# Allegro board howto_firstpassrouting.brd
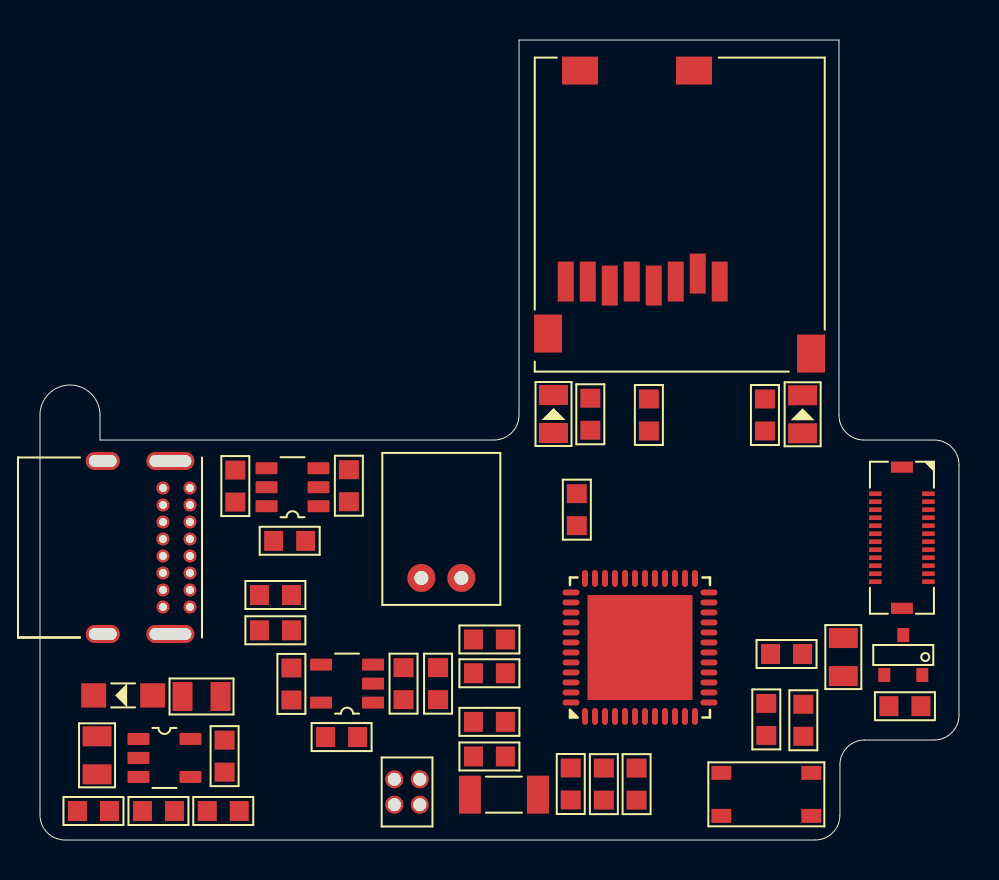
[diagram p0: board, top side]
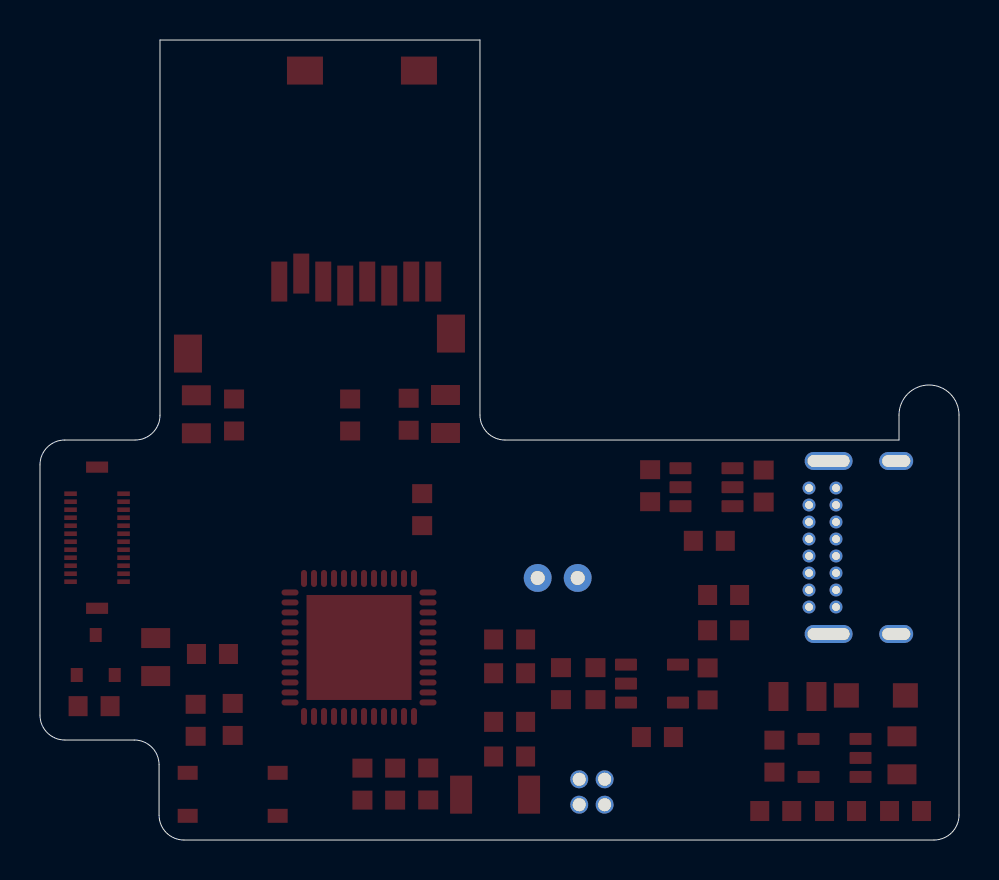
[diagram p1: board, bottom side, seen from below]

Outline 45.95 x 40 mm; copper layers: TOP, L2, L3, BOTTOM. Coordinates in mm from the lower left corner of the outline.
Outline path: 0,21.25 0,1.25 arc(0.37,0.37) 1.25,0 38.76,0 arc(39.64,0.36) 40,1.24 40,3.76 arc(40.36,4.64) 41.24,5 44.71,5 arc(45.59,5.36) 45.95,6.24 45.95,18.76 arc(45.59,19.64) 44.71,20 41.19,20 arc(40.32,20.36) 39.95,21.24 39.95,40 23.95,40 23.95,21.25 arc(23.59,20.37) 22.7,20 3,20 3,21.25 arc(1.5,22.75) 0,21.25

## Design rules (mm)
constraint set DEFAULT: min track width 0.127

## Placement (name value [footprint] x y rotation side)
C15  1uF  [CAP0603]  9.77 17.7 90 top
C16  1uF  [CAP0603]  18.18 7.82 270 top
C19  10uF  [CAP0805]  2.85 4.23 270 top
C20  2.2uF  [CAP0603]  12.57 7.8 90 top
C21  470pF  [CAP0603]  15.08 5.15 0 top
C23  100nF  [CAP0603]  22.47 8.34 180 top
C24  100nF  [CAP0603]  26.84 16.52 90 top
C25  100nF  [CAP0603]  37.33 9.3 0 top
C26  100nF  [CAP0603]  29.83 2.79 270 top
C27  1uF  [CAP0603]  22.47 10.03 180 top
C28  1uF  [CAP0603]  28.2 2.79 270 top
C29  100nF  [CAP0603]  36.32 6.03 90 top
C32  1uF  [CAP0603]  9.23 4.19 270 top
C33  9pF  [CAP0603]  22.47 4.18 180 top
C34  9pF  [CAP0603]  26.54 2.8 90 top
D1  GREEN  [DIO0805]  38.14 21.29 90 top
D2  GREEN  [DIO0805]  25.68 21.3 90 top
D3  SCHOTTKY_DIODE  [SOD-123FL]  4.16 7.23 180 top
J1  -  [USB4085-GF-A]  1.4 14.63 270 top
J2  HEADER VERT 2X2  [2X2-HEADER-50MIL-VERT]  18.36 2.4 270 top
J3  DF37NB-24DS-0.4V  [DF37NB-24DS-0]  43.1 15.11 270 top
J4  2-PIN-CON  [S2B-PH-K]  19.07 13.1 0 top
L1  10uH  [IND0805]  8.08 7.18 180 top
M2  NMOS  [SOT-23-3]  43.17 9.25 0 top
R7  86.6k  [RES0603]  2.67 1.45 0 top
R8  10k  [RES0603]  5.92 1.45 0 top
R9  5.1k  [RES0603]  11.77 10.49 0 top
R10  5.1k  [RES0603]  11.77 12.25 0 top
R11  5.1k  [RES0603]  12.49 14.96 180 top
R12  10k  [RES0603]  38.17 5.99 270 top
R13  10k  [RES0603]  9.16 1.45 0 top
R14  10k  [RES0603]  36.25 21.25 270 top
R15  1.5k  [RES0603]  27.52 21.29 270 top
R16  100k  [RES0603]  19.9 7.82 270 top
R17  100k  [RES0603]  22.47 5.91 0 top
R18  10k  [RES0603]  30.45 21.25 270 top
R19  150R  [RES0805]  40.17 9.15 90 top
R20  10k  [RES0603]  43.25 6.69 0 top
R21  10k  [RES0603]  15.45 17.71 90 top
S1  SPST-NO  [PTS815-SJM-250-SMTR-LFS]  36.32 2.28 0 top
SD2  -  [MEM2061]  30.14 27.92 0 top
U2  BQ21040  [SOT-23-6]  12.63 17.64 180 top
U4  MIC5205-3.3YM5-TR  [SOT-23-5]  15.35 7.82 180 top
U5  AP3012_IC  [SOT-23-5]  6.22 4.1 0 top
U7  ATSAMD21G18A-MF  [48QFN_7X7]  30 9.63 90 top
Y2  32.768 kHz  [2-SMD]  23.2 2.27 0 top

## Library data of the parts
C15 C16 C19-C21 C23-C29 C32-C34 = CAP1: tolerance: 10%
D1 D2 = SML-210MTT86
D3 = SCHOTTKY_DIODE
J1 = USB4085-GF-A
J2 = HEADER VERT 2X2
J3 = DF37NB-24DS-0.4V
J4 = 2-PIN-CON
L1 = IND: tolerance: 20%
M2 = NMOS
R7-R21 = RES1: tolerance: 1%
S1 = PTS815 SJM 250 SMTR LFS
SD2 = MEM2061
U2 = BQ21040
U4 = MIC5205-3.3YM5-TR
U5 = AP3012_IC
U7 = ATSAMD21G18A-MF
Y2 = CC5V-T1A-32.768KHZ-9PF: tolerance: 20%

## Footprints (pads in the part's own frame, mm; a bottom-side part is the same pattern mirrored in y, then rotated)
2-SMD
  rect 1.1x1.9 smd: 1(-1.7,0) 2(1.7,0)
2X2-HEADER-50MIL-VERT
  round 0.9 hole 0.65: 1(-0.635,0.635) 2(-0.635,-0.635) 3(0.635,0.635) 4(0.635,-0.635)
48QFN_7X7
  oval 0.851x0.3 smd: 1(-3.45,2.75) 2(-3.45,2.25) 3(-3.45,1.75) 4(-3.45,1.25) 5(-3.45,0.75) 6(-3.45,0.25) 7(-3.45,-0.25) 8(-3.45,-0.75) 9(-3.45,-1.25) 10(-3.45,-1.75) 11(-3.45,-2.25) 12(-3.45,-2.75) 25(3.45,-2.75) 26(3.45,-2.25) 27(3.45,-1.75) 28(3.45,-1.25) 29(3.45,-0.75) 30(3.45,-0.25) 31(3.45,0.25) 32(3.45,0.75) 33(3.45,1.25) 34(3.45,1.75) 35(3.45,2.25) 36(3.45,2.75)
  oval 0.3x0.851 smd: 13(-2.75,-3.45) 14(-2.25,-3.45) 15(-1.75,-3.45) 16(-1.25,-3.45) 17(-0.75,-3.45) 18(-0.25,-3.45) 19(0.25,-3.45) 20(0.75,-3.45) 21(1.25,-3.45) 22(1.75,-3.45) 23(2.25,-3.45) 24(2.75,-3.45) 37(2.75,3.45) 38(2.25,3.45) 39(1.75,3.45) 40(1.25,3.45) 41(0.75,3.45) 42(0.25,3.45) 43(-0.25,3.45) 44(-0.75,3.45) 45(-1.25,3.45) 46(-1.75,3.45) 47(-2.25,3.45) 48(-2.75,3.45)
  rect 5.25x5.25 smd: 49(0,0)
CAP0603
  rect 0.95x1.001 smd: 1(-0.8,0) 2(0.8,0)
CAP0805
  rrect 1x1.45 smd: 1(-0.95,0) 2(0.95,0)
DF37NB-24DS-0
  rect 0.23x0.63 smd: 1(-2.2,1.325) 2(-2.2,-1.325) 3(-1.8,1.325) 4(-1.8,-1.325) 5(-1.4,1.325) 6(-1.4,-1.325) 7(-1,1.325) 8(-1,-1.325) 9(-0.6,1.325) 10(-0.6,-1.325) 11(-0.2,1.325) 12(-0.2,-1.325) 13(0.2,1.325) 14(0.2,-1.325) 15(0.6,1.325) 16(0.6,-1.325) 17(1,1.325) 18(1,-1.325) 19(1.4,1.325) 20(1.4,-1.325) 21(1.8,1.325) 22(1.8,-1.325) 23(2.2,1.325) 24(2.2,-1.325)
  rect 0.56x1.1 smd: 25(-3.53,0) 26(3.53,0)
DIO0805
  rrect 1x1.45 smd: 1(-0.95,0) 2(0.95,0)
IND0805
  rrect 1x1.45 smd: 1(-0.95,0) 2(0.95,0)
MEM2061
  rect 0.8x2 smd: 1(3.85,0) 2(2.75,0.4) 3(1.65,0) 4(0.55,-0.2) 5(-0.55,0) 6(-1.65,-0.2) 7(-2.75,0) 8(-3.85,0)
  rect 1.4x1.9 smd: P1(-4.735,-2.6) P2(8.415,-3.6)
  rect 1.8x1.4 smd: SW1(-3.135,10.55) SW2(2.565,10.55)
PTS815-SJM-250-SMTR-LFS
  rect 1x0.7 smd: 1(-2.25,1.075) 2(2.25,1.075) 3(-2.25,-1.075) 4(2.25,-1.075)
RES0603
  rect 0.95x1.001 smd: 1(-0.8,0) 2(0.8,0)
RES0805
  rrect 1x1.45 smd: 1(-0.95,0) 2(0.95,0)
S2B-PH-K
  round 1.4 hole 0.7: 1(2,0) 2(0,0)
SOD-123FL
  rect 1.25x1.22 smd: 1(-1.475,0) 2(1.475,0)
SOT-23-3
  rect 0.6x0.7 smd: 1(0.95,-1) 2(0,1) 3(-0.95,-1)
SOT-23-5
  rrect 1.1x0.6 smd: 1(-1.3,0.95) 2(-1.3,0) 3(-1.3,-0.95) 4(1.3,-0.95) 5(1.3,0.95)
SOT-23-6
  rrect 1.1x0.6 smd: 1(-1.3,0.95) 2(-1.3,0) 3(-1.3,-0.95) 4(1.3,-0.95) 5(1.3,0) 6(1.3,0.95)
USB4085-GF-A
  oval 0.9x1.7 hole 0.6x1.4 unplated: (-4.325,1.74) (4.325,1.74)
  round 0.65 hole 0.4: A1(-2.975,6.1) A4(-2.125,6.1) A5(-1.275,6.1) A6(-0.425,6.1) A7(0.425,6.1) A8(1.275,6.1) A9(2.125,6.1) A12(2.975,6.1) B1(2.975,4.75) B4(2.125,4.75) B5(1.275,4.75) B6(0.425,4.75) B7(-0.425,4.75) B8(-1.275,4.75) B9(-2.125,4.75) B12(-2.975,4.75)
  oval 0.9x2.4 hole 0.6x2.1: MNT1(-4.325,5.12) MNT2(4.325,5.12)

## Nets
+3V3: C20.1 C23.1 C24.1 C25.1 C26.1 J2.3 J3.18 J3.20 R12.1 R18.1 SD2.4 U4.5(OUT) U7.6 U7.17 U7.36(VDDIO#36) U7.44
+12V0: C19.1 D3.2 R7.1 R19.1
+VBATT: C16.1 C32.1 J4.1 L1.1 R15.1 R16.1 U2.2 U4.1 U4.3 U5.5(VIN)
+VDDCORE: C27.1 U7.43
GND: C15.2 C16.2 C19.2 C20.2 C21.2 C23.2 C24.2 C25.2 C26.2 C27.2 C28.2 C29.2 C32.2 C33.2 C34.2 D1.2(K) J1.A1 J1.A12 J1.B1 J1.B12 J1.MNT1 J1.MNT2 J2.4 J3.1 J3.3 J3.13 J3.21 J3.24 J3.25 J3.26 J4.2 M2.1(S) R8.2 R9.2 R10.2 R11.2 R13.2 R17.2 R20.2 R21.2 S1.1 S1.3 SD2.6(VSS) SD2.P1 SD2.P2 SD2.SW2 U2.5 U4.2 U5.2 U7.5 U7.18 U7.35 U7.42 U7.49
+V_USB: C15.1 J1.A4 J1.A9 J1.B4 J1.B9(VBUS4) U2.6(VIN)
ADC_VBATT: R16.2 R17.1 U7.48
AREF: C28.1 U7.4
CS*: J3.17 U7.14
D_N: J1.A7 J1.B7 U7.33
D_P: J1.A6 J1.B6 U7.34
DB0: J3.12 U7.26
DB1: J3.11 U7.16
DB2: J3.10 U7.27
DB3: J3.9 U7.19
DB4: J3.8 U7.28
DB5: J3.7 U7.21
DB6: J3.6 U7.29
DB7: J3.5 U7.22
LCD_POWER_EN: R13.1 U5.4 U7.39
LCD_PWM: M2.3 R20.1 U7.20
LCD_RST: J3.2 U7.30
RD*: J3.14 U7.24
RS: J3.16 U7.23
SD_CARD_DETECT: R18.2 SD2.SW1 U7.13
SD_CS: SD2.2 U7.32
SD_MISO: SD2.7 U7.38
SD_MOSI: SD2.3 U7.31
SD_SCK: SD2.5 U7.37
SWCLK: J2.1 U7.45
SWDIO: J2.2 U7.46
WR*: J3.15 U7.15
N42146: J1.A5 R9.1
N42214: R11.1 U2.4
N42218: R21.1 U2.1
N42238: C21.1 U4.4
N42330: J1.B5 R10.1
N42350: D2.1 R15.2
N42414: D2.2(K) U2.3
N42648: D3.1 L1.2 U5.1
N42818: R7.2 R8.1 U5.3
N43960: C33.1 U7.1 Y2.1
N43976: C34.1 U7.2 Y2.2
N44106: C29.1 R12.2 S1.2 S1.4 U7.40
N44702: R14.1 U7.25
N44714: D1.1 R14.2
N46598: J3.22 R19.2
N46734: J3.23 M2.2

Pads without a net: J1 A8 B8; J3 4 19; SD2 1 8; U7 3 7 8 9 10 11 12 41 47
